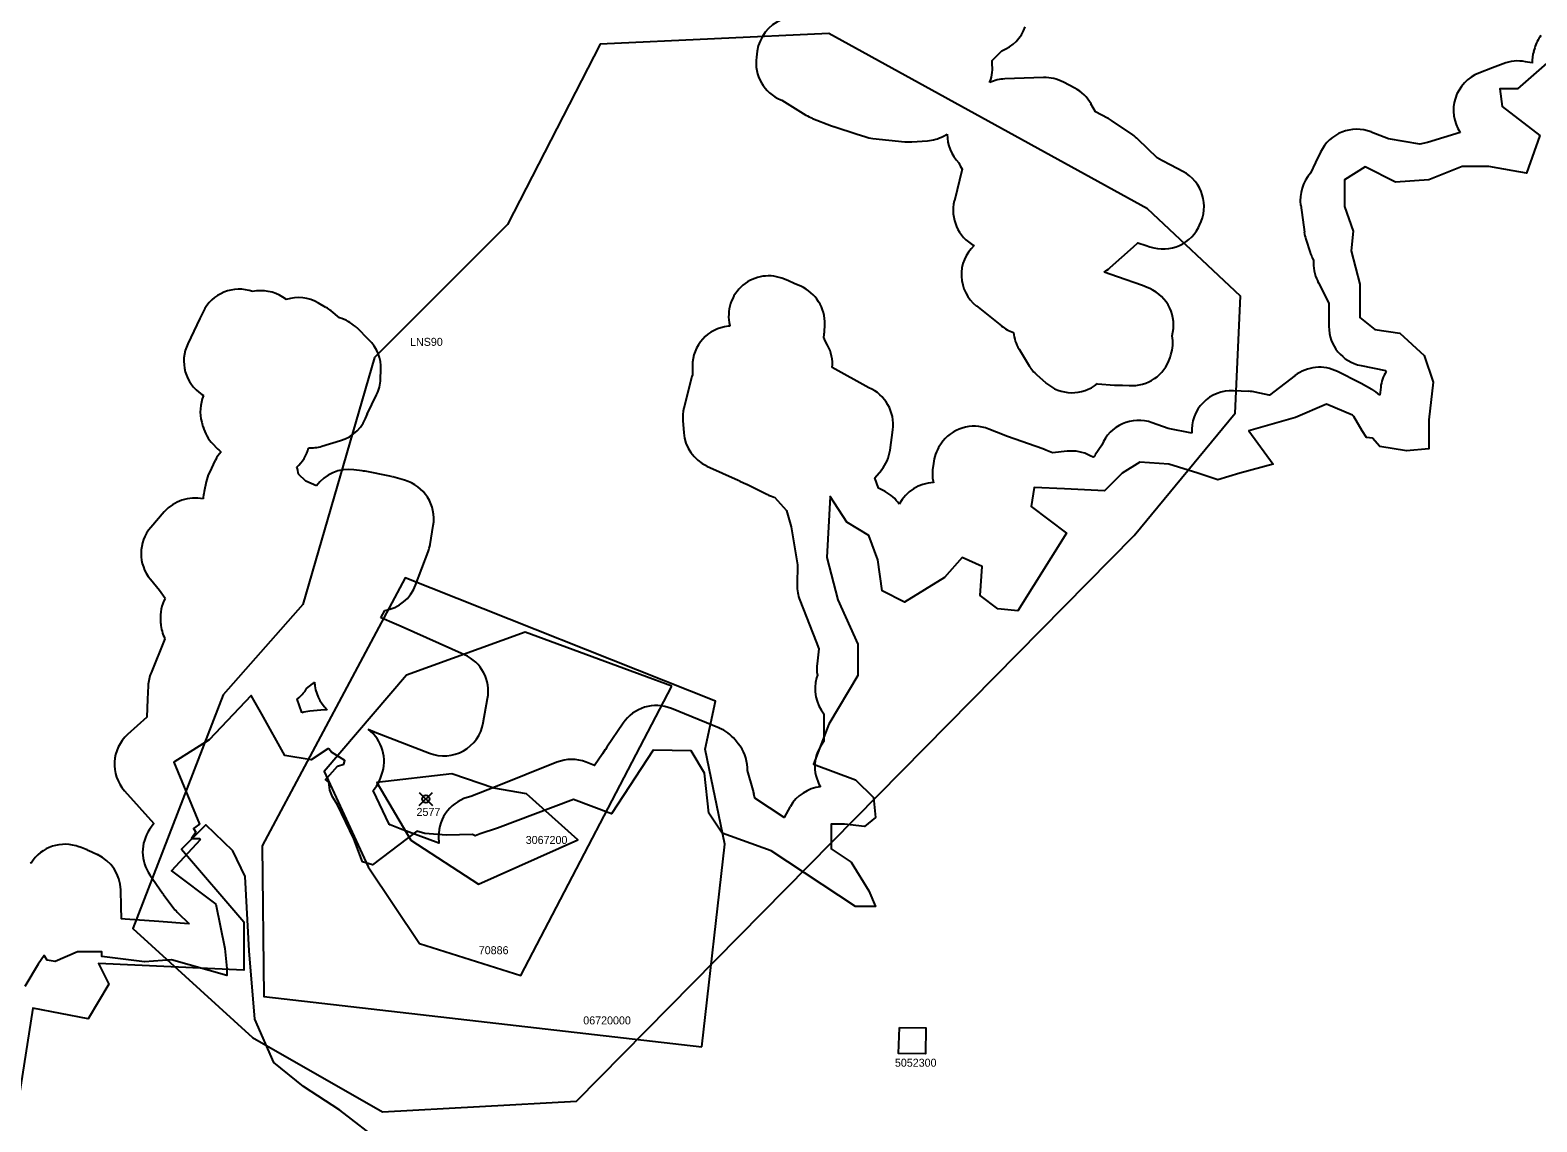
# Model space of a CAD drawing. Extents: x -546762 to -536351, y -1046851 to -1035695.
# Drawn here: x -544214 to -542331, y -1043037 to -1041672 of the extents above; entities that cross this region are included whole.
import ezdxf

# ---------------------------------------------------------------- set-up
doc = ezdxf.new("R2010")
doc.units = 0
for name, color, linetype in [('Vrstva 23', 7, 'Continuous'), ('Vrstva 24', 7, 'Continuous'), ('Vrstva 25', 7, 'Continuous'), ('Vrstva 40', 7, 'Continuous'), ('Vrstva 41', 7, 'Continuous'), ('Vrstva 44', 7, 'Continuous'), ('Vrstva 47', 7, 'Continuous'), ('Vrstva 48', 7, 'Continuous'), ('Vrstva 50', 7, 'Continuous')]:
    doc.layers.add(name, color=color, linetype=linetype)

msp = doc.modelspace()

# ---------------------------------------------------------------- linework, layer by layer
at = {"layer": 'Vrstva 23'}
for points in [[(-543305.3, -1041698.7), (-543306.3, -1041706.4)], [(-543006.6, -1041705.6), (-542999.4, -1041698.1)], [(-542333.6, -1041694.6), (-542334.9, -1041699.1)], [(-543011.8, -1041713.1), (-543011.7, -1041710.3)], [(-542373.1, -1041714.4), (-542386.5, -1041719.6), (-542403.3, -1041726.1)], [(-542336.9, -1041713.5), (-542345.4, -1041711.9)], [(-543014.8, -1041737.8), (-543014.5, -1041737.1)], [(-542947.6, -1041731.8), (-542995.9, -1041733.4)], [(-542908.4, -1041745), (-542922.6, -1041737.5)], [(-543276, -1041759.5), (-543274.5, -1041760.1), (-543244.7, -1041778.6)], [(-542867.4, -1041782.4), (-542882.7, -1041774.4), (-542888.2, -1041764.7)], [(-543236.4, -1041782.7), (-543212.4, -1041792)], [(-543209.8, -1041792.9), (-543180.3, -1041802.5)], [(-542835.9, -1041803.4), (-542862.5, -1041785.3)], [(-543180.3, -1041802.5), (-543171, -1041805.5)], [(-543160.8, -1041807.7), (-543121, -1041811.9)], [(-543112.2, -1041812.1), (-543092.6, -1041810.7)], [(-543072.7, -1041805.1), (-543067.8, -1041802.5)], [(-542799.5, -1041835.2), (-542805.6, -1041832), (-542829.1, -1041809)], [(-542426.9, -1041800.2), (-542467.8, -1041812.9), (-542477, -1041814.9), (-542516.4, -1041808.1), (-542538, -1041799.8)], [(-542601.2, -1041825), (-542607.4, -1041838), (-542613.8, -1041851.2)], [(-543049.2, -1041846.1), (-543059, -1041885.6)], [(-542773.4, -1041849.2), (-542788.2, -1041841.3), (-542799.5, -1041835.3)], [(-542626.1, -1041891.4), (-542621.5, -1041925.1)], [(-542753.9, -1041919), (-542752.5, -1041916.3)], [(-542864.1, -1041969), (-542835.1, -1041943.1), (-542829.6, -1041938.2), (-542819.1, -1041941.5), (-542819.1, -1041941.5)], [(-542619.6, -1041933.6), (-542614.3, -1041950.2)], [(-542611.6, -1041957), (-542610.1, -1041959.9)], [(-542855, -1041980.8), (-542871.8, -1041974.9)], [(-542864.8, -1041969.7), (-542864.3, -1041969.2)], [(-542823.7, -1041991.7), (-542855, -1041980.8)], [(-543266.2, -1041985.9), (-543271.1, -1041983.7)], [(-543254.4, -1041991), (-543259.1, -1041988.9), (-543266.1, -1041985.9)], [(-543251, -1041992.5), (-543254.3, -1041991)], [(-542814.8, -1041995.5), (-542820.1, -1041993.2)], [(-542604.9, -1041986), (-542603.8, -1041988.1), (-542591, -1042013.7), (-542590.9, -1042042.8)], [(-543893.9, -1042009), (-543898.3, -1042006.1)], [(-543844.4, -1042018.9), (-543853.6, -1042013.5)], [(-543031.4, -1042017.2), (-543000.2, -1042042.1)], [(-543998, -1042024.6), (-544002, -1042032.9), (-544017.1, -1042064.4)], [(-543824.5, -1042033), (-543827.5, -1042032), (-543837.9, -1042023.4)], [(-543790.7, -1042059.4), (-543805.6, -1042044.7)], [(-543339.7, -1042042.3), (-543341.6, -1042042.5)], [(-543221.4, -1042050.1), (-543221, -1042040.4)], [(-543217.4, -1042066.2), (-543220.8, -1042059.8)], [(-542978.1, -1042071), (-542965.5, -1042091.9)], [(-543386.4, -1042095), (-543386.4, -1042103.3), (-543386.9, -1042105.3), (-543397, -1042144.7)], [(-543386.4, -1042092), (-543386.4, -1042094.9)], [(-543165.9, -1042119.3), (-543211.6, -1042094.2)], [(-542789.4, -1042081.7), (-542788.3, -1042078.2)], [(-542550.6, -1042091.7), (-542520.1, -1042097.7), (-542519.4, -1042099.1)], [(-543776.2, -1042108.4), (-543775.8, -1042096.9)], [(-542955.8, -1042103.4), (-542945, -1042113)], [(-542880.1, -1042114.3), (-542858.7, -1042116.1)], [(-542633.2, -1042104.2), (-542664.9, -1042128.6), (-542665.5, -1042128.5), (-542682.8, -1042124.9)], [(-542552, -1042113.4), (-542580.1, -1042099.1)], [(-542537.3, -1042121.4), (-542550.5, -1042114.1)], [(-543999.5, -1042127.8), (-543997.4, -1042129.1)], [(-543792.7, -1042152.2), (-543781.1, -1042128.2)], [(-542848.9, -1042116), (-542840.5, -1042116.6)], [(-542690.8, -1042123.9), (-542710.1, -1042123.1)], [(-542526.1, -1042118.7), (-542527.3, -1042128.6)], [(-543999.7, -1042162.5), (-543998.1, -1042168.2)], [(-543398.4, -1042160.9), (-543397.2, -1042175.5)], [(-542762.2, -1042176.2), (-542791.9, -1042170.1), (-542811.7, -1042163.1)], [(-543985.8, -1042189.5), (-543980.6, -1042194.8)], [(-543849.6, -1042192.5), (-543826.2, -1042185.5)], [(-543139.3, -1042197.2), (-543135.9, -1042171.9)], [(-542948.4, -1042195.7), (-542992.5, -1042180.4), (-543006.3, -1042174.8), (-543015.7, -1042171.1)], [(-543075.9, -1042189.8), (-543077.1, -1042191.6)], [(-542918, -1042198.8), (-542936.4, -1042200.9), (-542944.6, -1042197.2)], [(-542883.7, -1042204.7), (-542884, -1042205.2), (-542885.3, -1042206.3), (-542889.1, -1042204.3)], [(-542874.8, -1042191.1), (-542882.9, -1042203.4)], [(-543982.7, -1042210), (-543990.1, -1042225.2)], [(-543799.1, -1042223.2), (-543809.5, -1042221.8)], [(-543764.6, -1042229.9), (-543795.6, -1042223.7)], [(-543368.2, -1042217.2), (-543329.3, -1042235), (-543327.2, -1042235.9)], [(-543145.5, -1042249.1), (-543153.7, -1042244.7), (-543158.2, -1042232.1), (-543150.2, -1042222.3)], [(-543085.2, -1042214), (-543086.1, -1042221.8)], [(-543994.2, -1042237.1), (-543996.8, -1042249.1)], [(-543856.3, -1042242), (-543869.4, -1042236.2), (-543878.8, -1042227.4)], [(-543746.2, -1042234.9), (-543761, -1042230.8)], [(-543327.1, -1042236), (-543318.6, -1042239.8)], [(-543316.6, -1042240.9), (-543293.5, -1042252.4)], [(-543085.6, -1042236.1), (-543085.2, -1042238)], [(-543288.8, -1042254.4), (-543284, -1042256.2)], [(-543283.9, -1042256.3), (-543268.9, -1042272.6), (-543262.9, -1042293.4), (-543255.1, -1042340.5), (-543255.6, -1042365.8)], [(-544046.5, -1042274.4), (-544063.3, -1042293.9)], [(-543714.3, -1042315.2), (-543710.3, -1042291.4)], [(-543732.4, -1042366), (-543716.8, -1042324.4)], [(-544063.9, -1042358.7), (-544052.6, -1042372.2), (-544045.2, -1042382.5)], [(-543252.1, -1042385), (-543231.7, -1042436.8), (-543228.3, -1042445.5), (-543230.5, -1042464.2)], [(-544051.3, -1042410.1), (-544051, -1042414.1)], [(-543775.8, -1042406.8), (-543771, -1042397.8)], [(-543671.2, -1042453.2), (-543750.6, -1042417.8), (-543762, -1042412.7), (-543771.8, -1042408.4)], [(-544045.8, -1042433), (-544063, -1042475.5)], [(-543868.6, -1042495.3), (-543861.4, -1042489.5)], [(-543230.1, -1042478.5), (-543231.1, -1042481.8)], [(-544067.4, -1042508.6), (-544068.4, -1042531.1), (-544092.3, -1042552.6)], [(-544066.7, -1042492.1), (-544067.4, -1042508.6)], [(-543874.5, -1042525.6), (-543874.7, -1042525.4), (-543880.2, -1042508.6), (-543877.9, -1042506.6)], [(-543647.8, -1042538.3), (-543642.3, -1042507.7)], [(-543846.2, -1042521.9), (-543864.6, -1042523.6)], [(-543352.7, -1042544.8), (-543412.6, -1042520.3)], [(-543222.1, -1042526.9), (-543222.2, -1042546.5), (-543222.3, -1042561.6)], [(-543791.7, -1042546.2), (-543783.7, -1042549.5)], [(-543473, -1042538.6), (-543493.3, -1042568.7), (-543495.1, -1042571.3)], [(-543782.7, -1042549.9), (-543715.1, -1042576.1)], [(-543329, -1042564.2), (-543333.1, -1042559.3)], [(-543495.3, -1042571.6), (-543498.8, -1042576.8), (-543508.7, -1042591.4), (-543519.3, -1042587.3)], [(-543776.2, -1042607.3), (-543774.9, -1042603.7)], [(-543555.9, -1042587.5), (-543632.7, -1042618.2), (-543632.7, -1042618.2), (-543663.4, -1042630.4)], [(-543310.4, -1042622.3), (-543317.5, -1042597.5), (-543317.6, -1042594.1)], [(-543765.3, -1042665.5), (-543765.6, -1042664.9), (-543765.6, -1042664.9), (-543785.4, -1042622.6)], [(-544096.1, -1042623), (-544059.7, -1042663.9), (-544064.9, -1042671.4)], [(-543264, -1042642.7), (-543271.8, -1042656.3), (-543308.3, -1042632.3), (-543309.4, -1042626.7)], [(-543703.6, -1042680.5), (-543703.4, -1042688.7), (-543751.7, -1042670.6), (-543751.7, -1042670.6), (-543764.2, -1042665.8)], [(-544144.3, -1042696.5), (-544152.5, -1042693.3)], [(-544130.1, -1042702.9), (-544141.8, -1042697.6)], [(-544064.5, -1042728.2), (-544048.6, -1042751)], [(-544095.3, -1042783.3), (-544099.8, -1042782.9), (-544100.3, -1042767.8), (-544100.9, -1042746.9)], [(-544047.7, -1042752.3), (-544034.4, -1042770)], [(-544029, -1042776.1), (-544016.2, -1042788.4), (-544015.6, -1042789.2), (-544053.3, -1042786.4), (-544095.3, -1042783.3)]]:
    msp.add_lwpolyline(points, dxfattribs=at)
for centre, start, end in [((-543255.8, -1041705.6), 112.7003, 172.0362), ((-543017.6, -1041651.6), 291.2904, 340.2497), ((-542285.6, -1041708.7), 143.9771, 163.5215), ((-542286.9, -1041713.3), 163.5215, 180.2978), ((-543256.8, -1041713.3), 172.0362, 247.491), ((-543061.4, -1041719.7), 339.6643, 7.6293), ((-543042.7, -1041671), 308.2845, 316.2219), ((-542354.9, -1041761), 78.943, 111.271), ((-542994.2, -1041783.4), 91.9214, 114.2475), ((-542945.9, -1041781.8), 62.2066, 91.9214), ((-542385.1, -1041772.7), 111.2621, 213.3774), ((-542931.7, -1041789.2), 29.3796, 62.2066), ((-543218.4, -1041736), 238.2956, 248.8555), ((-543194.4, -1041745.3), 248.8555, 251.9673), ((-542890.6, -1041826.7), 55.7748, 62.3787), ((-543164.8, -1041754.9), 251.9673, 251.9903), ((-543155.5, -1041758), 251.9903, 263.9018), ((-543115.7, -1041762.2), 263.9018, 273.9801), ((-543096, -1041760.8), 273.9801, 297.7679), ((-543017.8, -1041803.3), 179.0846, 224.3809), ((-542864.1, -1041844.7), 45.5468, 55.7748), ((-542556, -1041846.4), 68.8952, 154.562), ((-543007.9, -1041817.9), 204.0055, 214.2645), ((-542823, -1041879.4), 61.9538, 61.987), ((-542796.8, -1041893.3), 332.5924, 61.9895), ((-542576.6, -1041884.7), 138.0239, 187.7538), ((-543010.5, -1041897.7), 166.0571, 241.5061), ((-542798.2, -1041896), 245.3628, 332.5924), ((-542572, -1041918.4), 187.7538, 197.7371), ((-543000.2, -1041978.2), 133.0522, 231.4232), ((-542566.7, -1041934.9), 197.7371, 206.1511), ((-542560.2, -1041963.5), 175.9349, 206.7809), ((-543291.1, -1042029.6), 66.5099, 193.6877), ((-542897.9, -1041932.2), 301.4279, 311.4965), ((-542897.4, -1041931.8), 311.4965, 311.8271), ((-542871.6, -1042028), 70.6798, 70.6993), ((-543952.9, -1042046.2), 70.2068, 154.4131), ((-543925.6, -1042048.1), 56.9671, 102.0622), ((-543286.1, -1042031.7), 66.439, 66.5099), ((-543274.3, -1042036.8), 66.4068, 66.497), ((-543271, -1042038.3), 357.5697, 66.4068), ((-542840.3, -1042038.9), 66.1887, 70.6798), ((-542835, -1042041.2), 344.6552, 66.1887), ((-543878.9, -1042056.7), 59.6241, 107.5474), ((-543869.6, -1042062.1), 50.6071, 59.6241), ((-543840.7, -1042080.3), 45.4438, 71.0394), ((-543336.4, -1042092.2), 95.9275, 179.8024), ((-543289.7, -1042044.4), 176.5618, 177.5829), ((-543334.6, -1042092), 95.8607, 95.9275), ((-543271.4, -1042048), 349.3005, 357.5697), ((-543264.8, -1042083.5), 28.2413, 31.6778), ((-542969.1, -1042003), 231.4232, 251.2931), ((-542935.4, -1042045.1), 186.1062, 211.2372), ((-542836, -1042063.2), 342.5444, 10.0188), ((-542540.9, -1042042.6), 180.1821, 258.7636), ((-543972, -1042086), 154.3803, 236.67), ((-543825.7, -1042095.1), 357.8455, 45.4438), ((-543261.4, -1042089.8), 354.9899, 28.2413), ((-543336.4, -1042095.1), 179.8024, 179.8428), ((-542922.7, -1042066), 211.2372, 228.4842), ((-542837.1, -1042066.7), 266.1324, 342.5444), ((-542602.7, -1042143.8), 63.1911, 127.6649), ((-543826.2, -1042106.5), 334.2912, 357.8455), ((-542911.8, -1042075.6), 228.4842, 309.345), ((-542574.6, -1042158), 61.3139, 63.1911), ((-542476.5, -1042124.8), 149.0713, 172.9836), ((-543951.5, -1042149), 156.621, 195.7439), ((-543185.5, -1042165.3), 352.4455, 66.9298), ((-542854.4, -1042066.3), 264.9974, 276.2209), ((-542712.3, -1042173), 87.5362, 183.7113), ((-542693, -1042173.8), 78.2653, 87.5362), ((-542561.3, -1042165.2), 47.1703, 61.3139), ((-543348.5, -1042157), 165.7072, 184.4047), ((-543949.9, -1042154.6), 195.7439, 224.2376), ((-543840.5, -1042137.6), 286.6543, 343.0566), ((-543034.3, -1042217.5), 68.1774, 146.3099), ((-542828.6, -1042210.1), 70.3022, 157.641), ((-543347.4, -1042171.7), 184.4047, 245.4144), ((-543937.8, -1042232.1), 139.0286, 153.7527), ((-543944.8, -1042159.9), 224.2376, 231.9727), ((-543914.3, -1042181.4), 312.0833, 344.7495), ((-543863.9, -1042144.6), 267.4888, 286.6543), ((-543188.9, -1042190.6), 320.6123, 352.4455), ((-543035.5, -1042219.4), 146.3099, 173.8123), ((-542964.8, -1042243), 66.2304, 70.8126), ((-542912.5, -1042248.5), 62.0924, 96.306), ((-542841.1, -1042230.9), 146.698, 148.4149), ((-543945.3, -1042247.3), 153.7527, 168.1955), ((-543928.3, -1042234.1), 7.76, 18.2298), ((-543815.8, -1042271.4), 82.7261, 144.0176), ((-543805.4, -1042272.8), 78.6972, 82.7261), ((-543036.4, -1042227.2), 173.8123, 190.2843), ((-543774.4, -1042278.9), 74.4839, 78.6972), ((-543759.6, -1042283.1), 350.3501, 74.4839), ((-543306.3, -1042190.5), 245.3293, 245.4392), ((-543297.8, -1042194.4), 245.4392, 245.9115), ((-543294.3, -1042196.1), 241.3442, 243.5047), ((-543083.4, -1042287.9), 92.0351, 152.579), ((-544008.7, -1042307.2), 77.3858, 139.1182), ((-543947.8, -1042259.3), 168.1955, 178.8963), ((-543271.2, -1042207.6), 243.5047, 249.4827), ((-543247.1, -1042222.4), 222.5719, 222.697), ((-543169.1, -1042293.1), 34.3554, 61.8208), ((-544025.5, -1042326.6), 139.1182, 219.9551), ((-543763.6, -1042306.8), 339.4515, 350.3501), ((-543779.2, -1042348.5), 279.5186, 339.4515), ((-543205.6, -1042366.7), 178.927, 201.471), ((-544001.4, -1042406.6), 151.267, 184.0649), ((-544001.1, -1042410.5), 184.0649, 206.7116), ((-543792.1, -1042454.1), 65.9941, 70.9372), ((-543691.5, -1042498.8), 349.8105, 65.996), ((-543180.9, -1042470), 173.2549, 189.7608), ((-544016.7, -1042494.3), 157.8845, 177.4367), ((-543892.8, -1042450.6), 308.8967, 312.9372), ((-543808.7, -1042485.2), 182.2868, 226.8901), ((-543183.1, -1042495.7), 163.8419, 218.6277), ((-544017.5, -1042510.8), 177.4367, 177.467), ((-543911.3, -1042469.4), 311.9913, 328.8158), ((-543859.9, -1042573.4), 95.4403, 107.0437), ((-543841.4, -1042571.7), 91.7077, 95.4403), ((-543431.6, -1042566.6), 67.7595, 145.9435), ((-543821.7, -1042586.2), 339.5315, 53.1034), ((-543697, -1042529.4), 248.8292, 349.8105), ((-543371.7, -1042591.1), 39.5089, 67.7595), ((-544058.8, -1042589.8), 132.0236, 221.6986), ((-543764.7, -1042503.2), 247.6912, 248.8292), ((-543367.6, -1042596), 2.1932, 39.5089), ((-543183.3, -1042592.8), 141.3988, 210.3176), ((-543537.3, -1042633.9), 68.8573, 111.7603), ((-543453.8, -1042599.5), 145.6872, 146.0122), ((-543823.1, -1042589.8), 318.9831, 339.5315), ((-543358.5, -1042636), 10.7414, 15.8736), ((-543220.7, -1042667.7), 96.5829, 149.9428), ((-543653.6, -1042679.4), 101.2365, 181.1647), ((-544023.5, -1042699.5), 145.7398, 214.9414), ((-543781.8, -1042712.6), 69.3588, 70.6646), ((-544170.7, -1042739.9), 68.6584, 147.873), ((-544162.5, -1042743.1), 65.5375, 68.6584), ((-544190.6, -1042758), 116.62, 118.0582), ((-544150.8, -1042748.4), 1.7, 65.5375), ((-544007.6, -1042722.3), 214.9414, 216.756), ((-543994.3, -1042740.1), 216.756, 226.1639), ((-544099, -1042833.1), 85.7234, 85.7376), ((-544099, -1042833.1), 85.7376, 85.739)]:
    msp.add_arc(centre, 50, start, end, dxfattribs=at)
at = {"layer": 'Vrstva 24'}
msp.add_lwpolyline([(-542288.3, -1041687.4), (-542354.9, -1041745.7), (-542377.1, -1041745.7), (-542374.4, -1041768), (-542327.2, -1041804.1), (-542343.8, -1041851.3), (-542360.5, -1041848.5), (-542391, -1041842.9), (-542424.3, -1041842.9), (-542466, -1041859.6), (-542507.7, -1041862.4), (-542545.4, -1041843.5), (-542571.5, -1041859.6), (-542571.5, -1041892.9), (-542560.4, -1041923.5), (-542563.2, -1041948.4), (-542552.1, -1041990.1), (-542552.1, -1042031.7), (-542533.4, -1042046.7), (-542502.1, -1042051.2), (-542471.6, -1042079), (-542460.4, -1042112.3), (-542466, -1042159.5), (-542466, -1042195.6), (-542493.8, -1042198.4), (-542527.1, -1042192.8), (-542536.3, -1042182.2), (-542543.8, -1042181.7), (-542549.3, -1042173.4), (-542559.5, -1042155.5), (-542561.2, -1042153.6), (-542593.7, -1042140), (-542632.6, -1042156.7), (-542690.9, -1042173.4), (-542660.4, -1042215), (-542702, -1042226.1), (-542729.8, -1042234.5), (-542754.8, -1042226.1), (-542790.9, -1042215), (-542827, -1042212.2), (-542849.2, -1042226.1), (-542871.4, -1042248.3), (-542921.4, -1042245.6), (-542959.3, -1042244.2), (-542963, -1042267.8), (-542918.6, -1042301.1), (-542979.7, -1042398.3), (-543004.7, -1042395.5), (-543026.9, -1042378.8), (-543024.1, -1042342.7), (-543049.1, -1042331.6), (-543071.3, -1042356.6), (-543121.3, -1042387.2), (-543149.1, -1042373.3), (-543154.6, -1042334.4), (-543165.7, -1042303.9), (-543193.5, -1042287.2), (-543214.4, -1042255.1), (-543218.5, -1042331.6), (-543204.6, -1042384.4), (-543179.6, -1042439.9), (-543179.6, -1042478.8), (-543215.7, -1042539.9), (-543235.2, -1042589.9), (-543182.4, -1042609.3), (-543160.2, -1042631.5), (-543157.4, -1042656.5), (-543171.3, -1042667.6), (-543196.3, -1042664.9), (-543212.9, -1042664.9), (-543212.9, -1042695.4), (-543188, -1042712.1), (-543165.7, -1042748.2), (-543157.4, -1042767.6), (-543182.4, -1042767.6), (-543287.9, -1042698.2), (-543349, -1042676), (-543365.7, -1042651), (-543371.2, -1042601), (-543387.9, -1042573.2), (-543435.6, -1042572.1), (-543487.5, -1042652), (-543535.1, -1042633.8), (-543630.2, -1042669.8), (-543651.7, -1042676.8), (-543657.8, -1042679.2), (-543661.2, -1042677.6), (-543693.9, -1042678.5), (-543721, -1042676.5), (-543731, -1042673.5), (-543786.3, -1042715.8), (-543798.6, -1042711.7), (-543809.7, -1042683.2), (-543829.9, -1042640.7), (-543836.4, -1042630.5), (-543839.4, -1042622.1), (-543840.9, -1042612.4), (-543845, -1042608.9), (-543842.4, -1042606.5), (-543830, -1042592.1), (-543822.2, -1042589.6), (-543821, -1042585.3), (-543837.4, -1042574.7), (-543840.8, -1042570.5), (-543842.1, -1042570.6), (-543862.7, -1042584.3), (-543896, -1042578.8), (-543924.6, -1042527.2), (-543924.6, -1042527.5), (-543937.7, -1042503.8), (-543990.4, -1042559.3), (-544034.7, -1042587.5), (-544002.6, -1042664.8), (-544009.8, -1042670), (-544007.2, -1042674.6), (-544012.5, -1042682.5), (-544002.6, -1042682.5), (-544001.5, -1042684.3), (-544037.6, -1042723.2), (-543982.1, -1042764.8), (-543971, -1042820.3), (-543968.2, -1042845.3), (-543968.2, -1042853.7), (-544037.6, -1042834.2), (-544071, -1042837), (-544124.6, -1042830.3), (-544124.6, -1042824.5), (-544154.9, -1042824.5), (-544183, -1042836.4), (-544192.9, -1042834.9), (-544196.5, -1042829.1), (-544204.3, -1042839.8), (-544220.9, -1042867.6)], dxfattribs=at)
at = {"layer": 'Vrstva 25'}
msp.add_lwpolyline([(-543774.1, -1043063), (-543827.1, -1043022.1), (-543872.6, -1042992.6), (-543909.6, -1042962.6), (-543933.5, -1042908.4), (-543940.3, -1042823.1), (-543945.2, -1042730), (-543961, -1042698.2), (-543994.7, -1042665.8), (-544024.9, -1042696), (-543947.1, -1042786.8), (-543947.1, -1042847.4), (-544128.8, -1042838.7), (-544115.8, -1042864.7), (-544141.7, -1042907.9), (-544210.9, -1042894.9), (-544232.6, -1043033.4)], dxfattribs=at)
at = {"layer": 'Vrstva 40'}
msp.add_lwpolyline([(-543374.5, -1042943), (-543345.9, -1042689.8), (-543370.5, -1042571.2), (-543357.6, -1042511.1), (-543745.6, -1042357.1), (-543924, -1042692), (-543922.1, -1042880.2), (-543374.5, -1042943)], dxfattribs=at)
at = {"layer": 'Vrstva 41'}
msp.add_lwpolyline([(-543687.2, -1042602), (-543780.7, -1042612.6), (-543738.5, -1042684.6), (-543653.8, -1042739.7), (-543529.6, -1042684.4), (-543593.9, -1042626.9), (-543634.5, -1042619.9)], close=True, dxfattribs=at)
at = {"layer": 'Vrstva 44'}
msp.add_lwpolyline([(-543411.9, -1042492.5), (-543595.5, -1042424.9), (-543743.7, -1042478.7), (-543846.8, -1042599), (-543791.7, -1042718), (-543727.6, -1042813.9), (-543600.7, -1042854), (-543411.9, -1042492.5)], dxfattribs=at)
at = {"layer": 'Vrstva 47'}
msp.add_lwpolyline([(-543127.6, -1042918.8), (-543094.7, -1042919.4), (-543095.2, -1042951.8), (-543128.8, -1042951.2)], close=True, dxfattribs=at)
at = {"layer": 'Vrstva 48'}
msp.add_lwpolyline([(-543783.7, -1042081.5), (-543873.3, -1042390.2), (-543972.9, -1042503.1), (-544085.8, -1042795.2), (-543936.4, -1042931.3), (-543773.7, -1043024.3), (-543531.4, -1043011), (-542834.2, -1042303.9), (-542708.1, -1042151.2), (-542701.4, -1042005.1), (-542817.6, -1041895.6), (-543216, -1041676.5), (-543501.5, -1041689.8), (-543617.7, -1041915.5), (-543783.7, -1042081.5)], dxfattribs=at)
at = {"layer": 'Vrstva 50'}
for p, q in [((-543727.9, -1042641.5), (-543711.4, -1042625)), ((-543727.9, -1042625), (-543711.4, -1042641.5))]:
    msp.add_line(p, q, dxfattribs=at)
msp.add_circle((-543719.6, -1042633.3), 4.61, dxfattribs=at)

# ---------------------------------------------------------------- texts
at = {"layer": 'Vrstva 40'}
msp.add_text('06720000', height=10, dxfattribs=at).set_placement((-543522.8, -1042915))
at = {"layer": 'Vrstva 41'}
msp.add_text('3067200', height=10, dxfattribs=at).set_placement((-543594.7, -1042689.5))
at = {"layer": 'Vrstva 44'}
msp.add_text('70886', height=10, dxfattribs=at).set_placement((-543653.4, -1042827.3))
at = {"layer": 'Vrstva 47'}
msp.add_text('5052300', height=10, dxfattribs=at).set_placement((-543133.3, -1042967.9))
at = {"layer": 'Vrstva 48'}
msp.add_text('LNS90', height=10, dxfattribs=at).set_placement((-543739.3, -1042067))
at = {"layer": 'Vrstva 50'}
msp.add_text('2577', height=10, dxfattribs=at).set_placement((-543731.2, -1042654.5))

doc.saveas('drawing.dxf')
